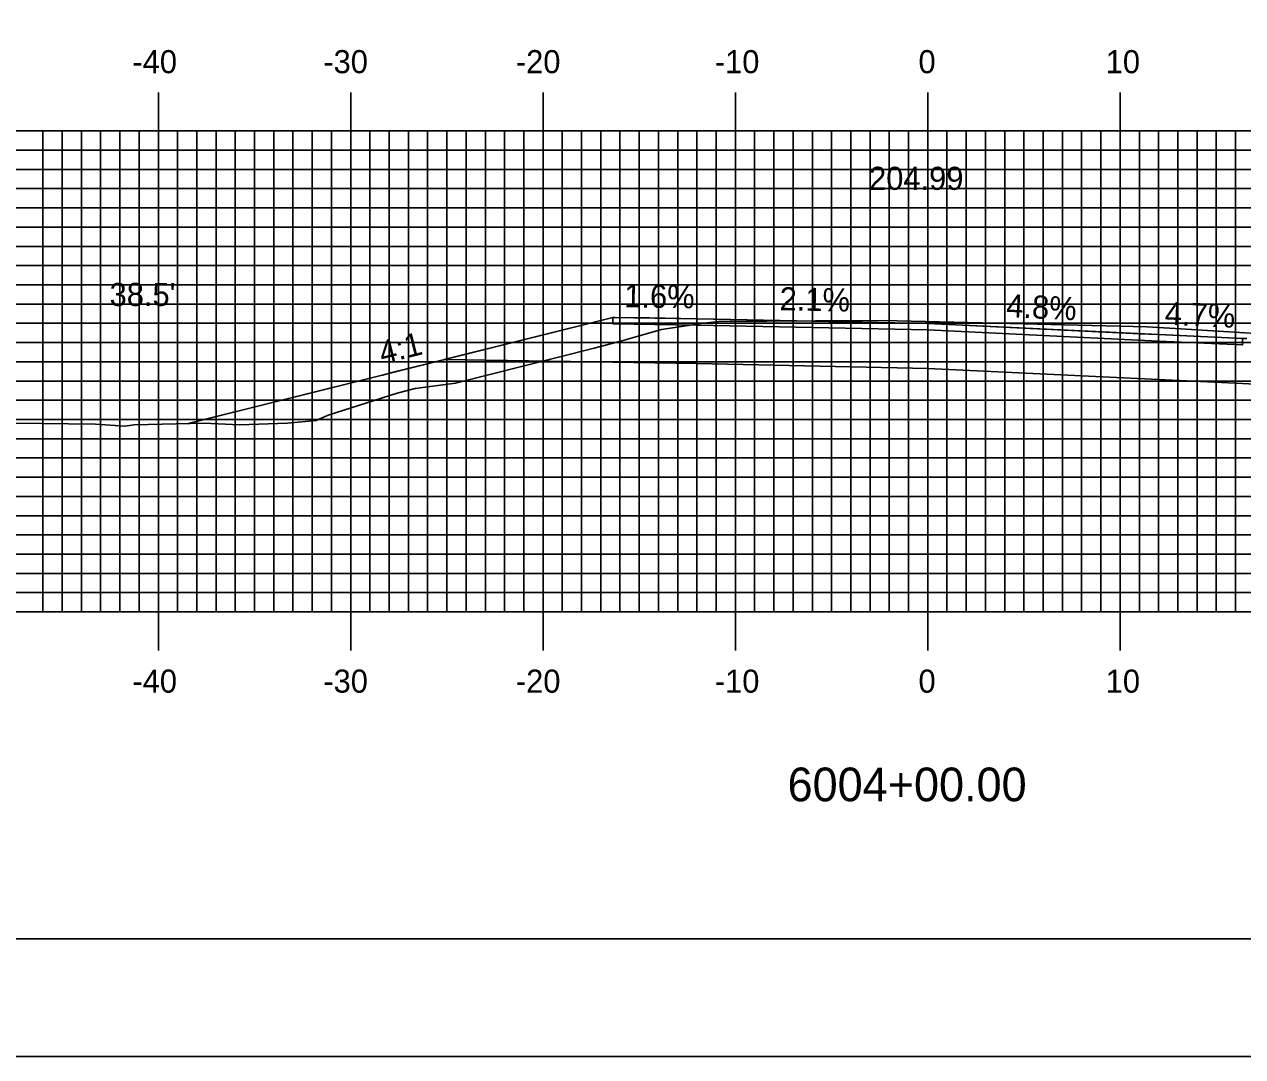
# Model space of a CAD drawing. Extents: x 852087 to 852430, y 366898 to 367118.
# Drawn here: x 852205.6 to 852268.9, y 366898.4 to 366952 of the extents above; entities that cross this region are included whole.
import ezdxf

# ---------------------------------------------------------------- set-up
doc = ezdxf.new("R2010")
doc.units = 0
for name, color, linetype in [('ANNOTATION', 7, 'Continuous'), ('BORDER', 7, 'Continuous'), ('D_Roadway_Centerline', 7, 'Continuous'), ('D_Roadway_Drive_SubGrade', 7, 'Continuous'), ('D_Roadway_Edge_Shoulder', 7, 'Continuous'), ('D_Roadway_Edge_TW', 7, 'Continuous'), ('D_Roadway_SlopeLines', 7, 'Continuous'), ('D_Roadway_SubGrade', 7, 'Continuous'), ('D_Text_Standard', 7, 'Continuous'), ('H_V ANNOTATION', 7, 'Continuous'), ('MAJOR', 7, 'Continuous'), ('MINOR', 7, 'Continuous'), ('PLOT BOUNDARY', 7, 'Continuous'), ('S_Roadway_Centerline', 7, 'Continuous')]:
    doc.layers.add(name, color=color, linetype=linetype)

msp = doc.modelspace()

# ---------------------------------------------------------------- linework, layer by layer
at = {"layer": 'BORDER'}
msp.add_lwpolyline([(852102.931, 366904.473), (852422.931, 366904.473), (852422.931, 367114.473), (852102.931, 367114.473)], close=True, dxfattribs=at)
at = {"layer": 'D_Roadway_Centerline'}
for points in [[(852214.078, 366931.26), (852214.078, 366931.26), (852214.73, 366931.423), (852224.163, 366933.781), (852224.179, 366933.785), (852224.495, 366933.864), (852224.609, 366933.893), (852227.836, 366934.7), (852236.163, 366936.781), (852236.281, 366936.779), (852238.068, 366936.751), (852240.514, 366936.711), (852240.532, 366936.711), (852240.575, 366936.71), (852252.531, 366936.461), (852252.575, 366936.459), (852263.536, 366935.934), (852264.493, 366935.888), (852264.532, 366935.886), (852264.545, 366935.885), (852268.9, 366935.68)], [(852268.9, 366935.68), (852269.116, 366935.682)]]:
    msp.add_lwpolyline(points, dxfattribs=at)
at = {"layer": 'D_Roadway_Drive_SubGrade'}
msp.add_line((852268.9, 366933.347), (852269.9, 366933.299), dxfattribs=at)
at = {"layer": 'D_Roadway_Edge_Shoulder'}
for points in [[(852240.531, 366936.711), (852236.162, 366936.781), (852236.163, 366936.448), (852240.531, 366936.378)], [(852264.531, 366935.886), (852268.9, 366935.68), (852268.9, 366935.347), (852264.531, 366935.553)]]:
    msp.add_lwpolyline(points, close=True, dxfattribs=at)
at = {"layer": 'D_Roadway_Edge_TW'}
msp.add_lwpolyline([(852240.531, 366936.378), (852240.531, 366936.711), (852252.531, 366936.461), (852264.531, 366935.886), (852264.531, 366935.553), (852252.531, 366936.128)], close=True, dxfattribs=at)
at = {"layer": 'D_Roadway_SlopeLines'}
msp.add_lwpolyline([(852236.162, 366936.781), (852224.163, 366933.781), (852214.078, 366931.26)], dxfattribs=at)
at = {"layer": 'D_Roadway_SubGrade'}
msp.add_lwpolyline([(852268.9, 366933.347), (852252.531, 366934.128), (852240.531, 366934.378), (852236.163, 366934.448), (852227.391, 366934.588), (852236.162, 366936.781), (852236.163, 366936.448), (852240.531, 366936.378), (852240.531, 366936.378), (852252.531, 366936.128), (852264.531, 366935.553), (852264.531, 366935.553), (852268.9, 366935.347)], dxfattribs=at)
at = {"layer": 'MAJOR'}
for p, q in [((852212.531, 366948.477), (852212.531, 366946.473)), ((852222.531, 366948.477), (852222.531, 366946.473)), ((852232.531, 366948.477), (852232.531, 366946.473)), ((852242.531, 366948.477), (852242.531, 366946.473)), ((852252.531, 366948.477), (852252.531, 366946.473)), ((852262.531, 366948.477), (852262.531, 366946.473)), ((852112.531, 366946.473), (852392.531, 366946.473)), ((852112.531, 366946.473), (852392.531, 366946.473)), ((852212.531, 366921.473), (852212.531, 366946.473)), ((852222.531, 366921.473), (852222.531, 366946.473)), ((852232.531, 366921.473), (852232.531, 366946.473)), ((852242.531, 366921.473), (852242.531, 366946.473)), ((852252.531, 366921.473), (852252.531, 366946.473)), ((852262.531, 366921.473), (852262.531, 366946.473)), ((852112.531, 366941.473), (852392.531, 366941.473)), ((852112.531, 366936.473), (852392.531, 366936.473)), ((852112.531, 366931.473), (852392.531, 366931.473)), ((852112.531, 366926.473), (852392.531, 366926.473)), ((852112.531, 366921.473), (852392.531, 366921.473)), ((852112.531, 366921.473), (852392.531, 366921.473)), ((852212.531, 366919.469), (852212.531, 366921.473)), ((852222.531, 366919.469), (852222.531, 366921.473)), ((852232.531, 366919.469), (852232.531, 366921.473)), ((852242.531, 366919.469), (852242.531, 366921.473)), ((852252.531, 366919.469), (852252.531, 366921.473)), ((852262.531, 366919.469), (852262.531, 366921.473))]:
    msp.add_line(p, q, dxfattribs=at)
at = {"layer": 'MINOR'}
for p, q in [((852206.531, 366921.473), (852206.531, 366946.473)), ((852207.531, 366921.473), (852207.531, 366946.473)), ((852208.531, 366921.473), (852208.531, 366946.473)), ((852209.531, 366921.473), (852209.531, 366946.473)), ((852210.531, 366921.473), (852210.531, 366946.473)), ((852211.531, 366921.473), (852211.531, 366946.473)), ((852213.531, 366921.473), (852213.531, 366946.473)), ((852214.531, 366921.473), (852214.531, 366946.473)), ((852215.531, 366921.473), (852215.531, 366946.473)), ((852216.531, 366921.473), (852216.531, 366946.473)), ((852217.531, 366921.473), (852217.531, 366946.473)), ((852218.531, 366921.473), (852218.531, 366946.473)), ((852219.531, 366921.473), (852219.531, 366946.473)), ((852220.531, 366921.473), (852220.531, 366946.473)), ((852221.531, 366921.473), (852221.531, 366946.473)), ((852223.531, 366921.473), (852223.531, 366946.473)), ((852224.531, 366921.473), (852224.531, 366946.473)), ((852225.531, 366921.473), (852225.531, 366946.473)), ((852226.531, 366921.473), (852226.531, 366946.473)), ((852227.531, 366921.473), (852227.531, 366946.473)), ((852228.531, 366921.473), (852228.531, 366946.473)), ((852229.531, 366921.473), (852229.531, 366946.473)), ((852230.531, 366921.473), (852230.531, 366946.473)), ((852231.531, 366921.473), (852231.531, 366946.473)), ((852233.531, 366921.473), (852233.531, 366946.473)), ((852234.531, 366921.473), (852234.531, 366946.473)), ((852235.531, 366921.473), (852235.531, 366946.473)), ((852236.531, 366921.473), (852236.531, 366946.473)), ((852237.531, 366921.473), (852237.531, 366946.473)), ((852238.531, 366921.473), (852238.531, 366946.473)), ((852239.531, 366921.473), (852239.531, 366946.473)), ((852240.531, 366921.473), (852240.531, 366946.473)), ((852241.531, 366921.473), (852241.531, 366946.473)), ((852243.531, 366921.473), (852243.531, 366946.473)), ((852244.531, 366921.473), (852244.531, 366946.473)), ((852245.531, 366921.473), (852245.531, 366946.473)), ((852246.531, 366921.473), (852246.531, 366946.473)), ((852247.531, 366921.473), (852247.531, 366946.473)), ((852248.531, 366921.473), (852248.531, 366946.473)), ((852249.531, 366921.473), (852249.531, 366946.473)), ((852250.531, 366921.473), (852250.531, 366946.473)), ((852251.531, 366921.473), (852251.531, 366946.473)), ((852253.531, 366921.473), (852253.531, 366946.473)), ((852254.531, 366921.473), (852254.531, 366946.473)), ((852255.531, 366921.473), (852255.531, 366946.473)), ((852256.531, 366921.473), (852256.531, 366946.473)), ((852257.531, 366921.473), (852257.531, 366946.473)), ((852258.531, 366921.473), (852258.531, 366946.473)), ((852259.531, 366921.473), (852259.531, 366946.473)), ((852260.531, 366921.473), (852260.531, 366946.473)), ((852261.531, 366921.473), (852261.531, 366946.473)), ((852263.531, 366921.473), (852263.531, 366946.473)), ((852264.531, 366921.473), (852264.531, 366946.473)), ((852265.531, 366921.473), (852265.531, 366946.473)), ((852266.531, 366921.473), (852266.531, 366946.473)), ((852267.531, 366921.473), (852267.531, 366946.473)), ((852268.531, 366921.473), (852268.531, 366946.473)), ((852112.531, 366945.473), (852392.531, 366945.473)), ((852112.531, 366944.473), (852392.531, 366944.473)), ((852112.531, 366943.473), (852392.531, 366943.473)), ((852112.531, 366942.473), (852392.531, 366942.473)), ((852112.531, 366940.473), (852392.531, 366940.473)), ((852112.531, 366939.473), (852392.531, 366939.473)), ((852112.531, 366938.473), (852392.531, 366938.473)), ((852112.531, 366937.473), (852392.531, 366937.473)), ((852112.531, 366935.473), (852392.531, 366935.473)), ((852112.531, 366934.473), (852392.531, 366934.473)), ((852112.531, 366933.473), (852392.531, 366933.473)), ((852112.531, 366932.473), (852392.531, 366932.473)), ((852112.531, 366930.473), (852392.531, 366930.473)), ((852112.531, 366929.473), (852392.531, 366929.473)), ((852112.531, 366928.473), (852392.531, 366928.473)), ((852112.531, 366927.473), (852392.531, 366927.473)), ((852112.531, 366925.473), (852392.531, 366925.473)), ((852112.531, 366924.473), (852392.531, 366924.473)), ((852112.531, 366923.473), (852392.531, 366923.473)), ((852112.531, 366922.473), (852392.531, 366922.473))]:
    msp.add_line(p, q, dxfattribs=at)
at = {"layer": 'PLOT BOUNDARY'}
msp.add_lwpolyline([(852086.744, 366898.355), (852426.744, 366898.355), (852426.744, 367118.355), (852086.744, 367118.355)], close=True, dxfattribs=at)
at = {"layer": 'S_Roadway_Centerline'}
msp.add_lwpolyline([(852205.055, 366931.276), (852209.269, 366931.23), (852210.797, 366931.119), (852211.272, 366931.203), (852214.916, 366931.277), (852216.743, 366931.195), (852219.244, 366931.288), (852220.731, 366931.422), (852221.362, 366931.7), (852224.951, 366932.847), (852225.888, 366933.085), (852227.982, 366933.354), (852235.195, 366935.178), (852236.63, 366935.556), (852238.682, 366936.144), (852240.777, 366936.461), (852241.654, 366936.571), (852246.699, 366936.604), (852250.187, 366936.618), (852255.361, 366936.492), (852263.925, 366936.286), (852265.692, 366936.178), (852270.959, 366935.859)], dxfattribs=at)

# ---------------------------------------------------------------- texts
at = {"layer": 'ANNOTATION'}
for s, rotation, p in [('1.6%', 359.08223, (852236.746, 366937.306)), ('2.1%', 358.80363, (852244.82, 366937.155)), ('4.8%', 357.2567, (852256.59, 366936.801)), ('4.7%', 357.30021, (852264.834, 366936.406)), ('4:1', 14.03602, (852224.175, 366934.334))]:
    msp.add_text(s, height=1.2, rotation=rotation, dxfattribs=at).set_placement(p)
at = {"layer": 'D_Roadway_Centerline'}
for s, p in [('C', (852252.526, 366936.461)), ('L', (852252.531, 366936.454))]:
    msp.add_text(s, height=0.0146, dxfattribs=at).set_placement(p)
at = {"layer": 'D_Text_Standard'}
msp.add_text("38.5'", height=1.2, dxfattribs=at).set_placement((852209.997, 366937.374))
at = {"layer": 'H_V ANNOTATION'}
for s, height, p in [('-40', 1.2, (852211.182, 366949.473)), ('-30', 1.2, (852221.107, 366949.473)), ('-20', 1.2, (852231.118, 366949.473)), ('-10', 1.2, (852241.461, 366949.473)), ('0', 1.2, (852252.049, 366949.473)), ('10', 1.2, (852261.782, 366949.473)), ('204.99', 1.2, (852249.48, 366943.409)), ('-40', 1.2, (852211.182, 366917.273)), ('-30', 1.2, (852221.107, 366917.273)), ('-20', 1.2, (852231.118, 366917.273)), ('-10', 1.2, (852241.461, 366917.273)), ('0', 1.2, (852252.049, 366917.273)), ('10', 1.2, (852261.782, 366917.273)), ('6004+00.00', 1.75, (852245.243, 366911.629))]:
    msp.add_text(s, height=height, dxfattribs=at).set_placement(p)
at = {"layer": 'S_Roadway_Centerline'}
for s, p in [('C', (852263.92, 366936.286)), ('C', (852263.92, 366936.286)), ('L', (852263.925, 366936.279)), ('L', (852263.925, 366936.279))]:
    msp.add_text(s, height=0.0146, dxfattribs=at).set_placement(p)

doc.saveas('drawing.dxf')
